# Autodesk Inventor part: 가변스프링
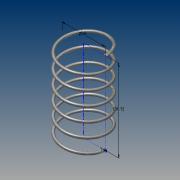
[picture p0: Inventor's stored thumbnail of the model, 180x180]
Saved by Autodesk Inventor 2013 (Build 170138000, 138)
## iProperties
Created: 2016-12
Part Number: 가변스프링
Material: 스테인리스강
Document SubType Name: Modeling
Designer: Administrator
Mass: 1.90072 g
Surface Area: 9.47236 cm^2
Volume: 0.235238 cm^3
Density: 8.08 g/cm^3
Author: Administrator
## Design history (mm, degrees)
sketch "스케치1"
  geometry: L1 (0, 0)-(8, 0); L2 (8, 0)-(8, 30.5); L3 (8, 30.5)-(0, 30.5); L4 (0, 30.5)-(0, 0); C1 r 0.5 at (8, 0)
  constraints: 8 end point, 2 parallel, 1 centre point, 1 coincident, 1 horizontal, 1 perpendicular
  dimensions: "d0" = 1 diameter of C1; "d1" = 16 diameter of L2 L4; "d2" = 30.5 distance between parallel lines of L3 L1 (derived)
feature "코일1" pitch "d3" = 10; turns "d5" = 6; dims "d4" = 30.5 (= d2), "d6" = 0, angle "d7" = 90 deg, angle "d8" = 90 deg, "d9" = 0, "d10" = 0
sketch "스케치2"
  geometry: L1 (-7.5, 0)-(-8.5, 0) reference; 1 further point
  constraints: 1 horizontal alignment
extrude "돌출1" cut sketch "스케치2" distance "d11" = 10; taper "d12" = 0 deg
node "작업 평면1"
sketch "스케치3"
  geometry: L1 (-0.5, 0)-(0.5, 0) reference; 1 further point
  constraints: 1 horizontal alignment
extrude "돌출2" cut sketch "스케치3" distance "d14" = 10; taper "d15" = 0 deg
node "솔리드1"
node "절단 모서리 투영1"
node "절단 모서리 투영2"
other parameters: "d13" = 90 deg
